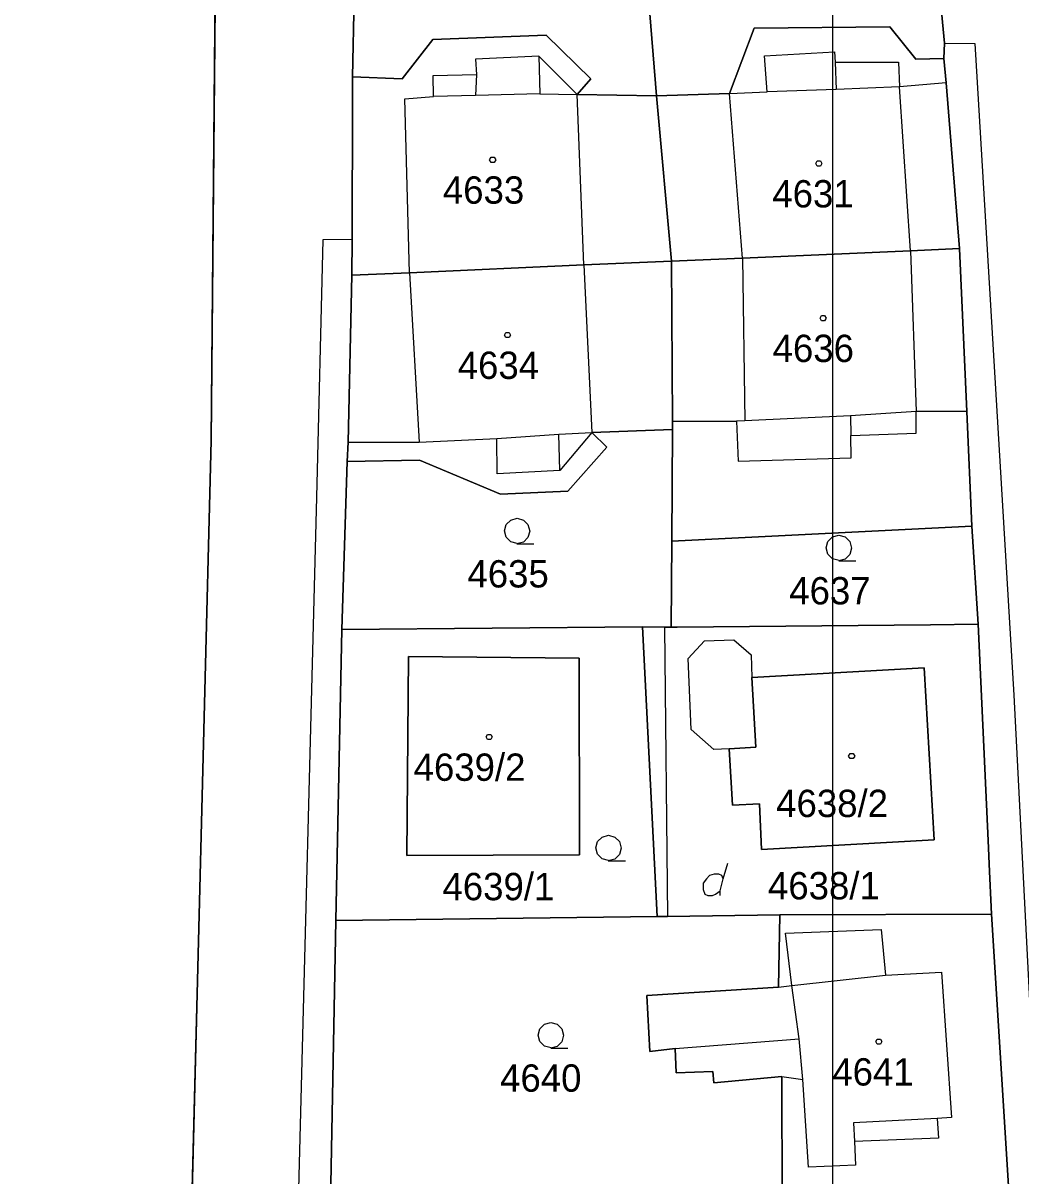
# Model space of a CAD drawing. Extents: x -263587 to -261993, y -1238795 to -1236748.
# Drawn here: x -262742.4 to -262684, y -1237554.8 to -1237487.3 of the extents above; entities that cross this region are included whole.
import ezdxf

# ---------------------------------------------------------------- set-up
doc = ezdxf.new("R2010")
doc.units = 0
for name, color, linetype in [('Vrstva 1', 7, 'Continuous'), ('Vrstva 2', 7, 'Continuous'), ('Vrstva 3', 7, 'Continuous'), ('Vrstva 51', 7, 'Continuous')]:
    doc.layers.add(name, color=color, linetype=linetype)

msp = doc.modelspace()

# ---------------------------------------------------------------- linework, layer by layer
at = {"layer": 'Vrstva 1'}
for p, q in [((-262731.39, -1237511.76), (-262731.08, -1237477.74)), ((-262731.08, -1237477.74), (-262731.39, -1237511.76)), ((-262689.31, -1237479.28), (-262688.48, -1237488.5)), ((-262688.48, -1237488.5), (-262689.31, -1237479.28)), ((-262705.33, -1237491.59), (-262706.28, -1237479.89)), ((-262706.28, -1237479.89), (-262705.33, -1237491.59)), ((-262723.11, -1237490.47), (-262722.91, -1237480.33)), ((-262722.91, -1237480.33), (-262723.11, -1237490.47)), ((-262711.79, -1237488.04), (-262718.41, -1237488.29)), ((-262718.41, -1237488.29), (-262711.79, -1237488.04)), ((-262709.18, -1237490.59), (-262711.79, -1237488.04)), ((-262711.79, -1237488.04), (-262709.18, -1237490.59)), ((-262701.05, -1237491.45), (-262699.62, -1237487.63)), ((-262699.62, -1237487.63), (-262701.05, -1237491.45)), ((-262699.62, -1237487.63), (-262691.67, -1237487.54)), ((-262691.67, -1237487.54), (-262699.62, -1237487.63)), ((-262691.67, -1237487.54), (-262690.15, -1237489.44)), ((-262690.15, -1237489.44), (-262691.67, -1237487.54)), ((-262718.41, -1237488.29), (-262720.21, -1237490.6)), ((-262720.21, -1237490.6), (-262718.41, -1237488.29)), ((-262688.48, -1237488.5), (-262688.52, -1237489.4)), ((-262688.52, -1237489.4), (-262688.48, -1237488.5)), ((-262688.48, -1237488.5), (-262686.71, -1237488.52)), ((-262686.71, -1237488.52), (-262684.42, -1237526.68)), ((-262712.22, -1237489.27), (-262715.92, -1237489.44)), ((-262715.92, -1237489.44), (-262715.86, -1237490.34)), ((-262709.98, -1237491.5), (-262712.22, -1237489.27)), ((-262712.22, -1237489.27), (-262712.16, -1237491.46)), ((-262699.01, -1237489.25), (-262694.91, -1237489.01)), ((-262698.86, -1237491.36), (-262699.01, -1237489.25)), ((-262694.91, -1237489.01), (-262694.88, -1237489.62)), ((-262690.15, -1237489.44), (-262688.52, -1237489.4)), ((-262688.52, -1237489.4), (-262690.15, -1237489.44)), ((-262688.52, -1237489.4), (-262688.38, -1237490.82)), ((-262688.38, -1237490.82), (-262688.52, -1237489.4)), ((-262694.88, -1237489.62), (-262694.81, -1237491.21)), ((-262694.88, -1237489.62), (-262691.17, -1237489.62)), ((-262691.17, -1237489.62), (-262691.12, -1237491.05)), ((-262720.21, -1237490.6), (-262723.11, -1237490.47)), ((-262723.11, -1237490.47), (-262720.21, -1237490.6)), ((-262723.11, -1237491.85), (-262723.11, -1237490.47)), ((-262723.11, -1237490.47), (-262723.11, -1237491.85)), ((-262718.39, -1237490.4), (-262715.86, -1237490.34)), ((-262718.37, -1237491.62), (-262718.39, -1237490.4)), ((-262715.86, -1237490.34), (-262715.92, -1237491.56)), ((-262709.98, -1237491.5), (-262709.18, -1237490.59)), ((-262709.18, -1237490.59), (-262709.98, -1237491.5)), ((-262688.38, -1237490.82), (-262691.12, -1237491.05)), ((-262688.38, -1237490.82), (-262687.6, -1237500.52)), ((-262687.6, -1237500.52), (-262688.38, -1237490.82)), ((-262712.16, -1237491.46), (-262715.92, -1237491.56)), ((-262712.16, -1237491.46), (-262709.98, -1237491.5)), ((-262705.33, -1237491.59), (-262709.98, -1237491.5)), ((-262709.98, -1237491.5), (-262705.33, -1237491.59)), ((-262709.59, -1237501.48), (-262709.98, -1237491.5)), ((-262705.33, -1237491.59), (-262701.05, -1237491.45)), ((-262701.05, -1237491.45), (-262705.33, -1237491.59)), ((-262701.05, -1237491.45), (-262698.86, -1237491.36)), ((-262700.29, -1237501.09), (-262701.05, -1237491.45)), ((-262694.81, -1237491.21), (-262698.86, -1237491.36)), ((-262691.12, -1237491.05), (-262694.81, -1237491.21)), ((-262690.47, -1237500.66), (-262691.12, -1237491.05)), ((-262723.14, -1237499.99), (-262723.11, -1237491.85)), ((-262723.11, -1237491.85), (-262723.14, -1237499.99)), ((-262720.06, -1237491.76), (-262718.37, -1237491.62)), ((-262719.79, -1237501.94), (-262720.06, -1237491.76)), ((-262715.92, -1237491.56), (-262718.37, -1237491.62)), ((-262704.45, -1237501.26), (-262705.33, -1237491.59)), ((-262705.33, -1237491.59), (-262704.45, -1237501.26)), ((-262724.85, -1237500.02), (-262725.22, -1237515.08)), ((-262723.14, -1237499.99), (-262724.85, -1237500.02)), ((-262723.15, -1237502.09), (-262723.14, -1237499.99)), ((-262723.14, -1237499.99), (-262723.15, -1237502.09)), ((-262690.47, -1237500.66), (-262700.29, -1237501.09)), ((-262700.29, -1237501.09), (-262690.47, -1237500.66)), ((-262687.6, -1237500.52), (-262690.47, -1237500.66)), ((-262690.47, -1237500.66), (-262687.6, -1237500.52)), ((-262690.47, -1237500.66), (-262690.13, -1237510.06)), ((-262687.6, -1237500.52), (-262687.17, -1237510.07)), ((-262687.17, -1237510.07), (-262687.6, -1237500.52)), ((-262719.79, -1237501.94), (-262709.59, -1237501.48)), ((-262709.59, -1237501.48), (-262719.79, -1237501.94)), ((-262709.59, -1237501.48), (-262704.45, -1237501.26)), ((-262704.45, -1237501.26), (-262709.59, -1237501.48)), ((-262709.59, -1237501.48), (-262709.12, -1237511.29)), ((-262700.29, -1237501.09), (-262704.45, -1237501.26)), ((-262704.45, -1237501.26), (-262700.29, -1237501.09)), ((-262704.39, -1237510.63), (-262704.45, -1237501.26)), ((-262704.45, -1237501.26), (-262704.39, -1237510.63)), ((-262700.29, -1237501.09), (-262700.17, -1237510.62)), ((-262723.37, -1237511.87), (-262723.15, -1237502.09)), ((-262723.15, -1237502.09), (-262723.37, -1237511.87)), ((-262723.15, -1237502.09), (-262719.79, -1237501.94)), ((-262719.79, -1237501.94), (-262723.15, -1237502.09)), ((-262719.79, -1237501.94), (-262719.21, -1237511.86)), ((-262693.97, -1237510.33), (-262700.17, -1237510.62)), ((-262690.13, -1237510.06), (-262693.97, -1237510.33)), ((-262693.97, -1237510.33), (-262693.96, -1237511.48)), ((-262687.17, -1237510.07), (-262690.13, -1237510.06)), ((-262690.13, -1237511.34), (-262690.13, -1237510.06)), ((-262687.17, -1237510.07), (-262686.87, -1237516.78)), ((-262686.87, -1237516.78), (-262687.17, -1237510.07)), ((-262704.4, -1237511.12), (-262704.39, -1237510.63)), ((-262704.39, -1237510.63), (-262704.4, -1237511.12)), ((-262704.39, -1237510.63), (-262700.64, -1237510.64)), ((-262700.17, -1237510.62), (-262700.64, -1237510.64)), ((-262700.64, -1237510.64), (-262700.55, -1237512.98)), ((-262732.21, -1237544.17), (-262731.39, -1237511.76)), ((-262731.39, -1237511.76), (-262732.21, -1237544.17)), ((-262719.21, -1237511.86), (-262714.68, -1237511.65)), ((-262714.68, -1237511.65), (-262711.05, -1237511.4)), ((-262714.66, -1237513.72), (-262714.68, -1237511.65)), ((-262711.05, -1237511.4), (-262709.12, -1237511.29)), ((-262710.98, -1237513.53), (-262711.05, -1237511.4)), ((-262709.12, -1237511.29), (-262710.98, -1237513.53)), ((-262704.4, -1237511.12), (-262709.12, -1237511.29)), ((-262709.12, -1237511.29), (-262704.4, -1237511.12)), ((-262709.12, -1237511.29), (-262708.24, -1237512.15)), ((-262708.24, -1237512.15), (-262709.12, -1237511.29)), ((-262704.43, -1237517.66), (-262704.4, -1237511.12)), ((-262704.4, -1237511.12), (-262704.43, -1237517.66)), ((-262693.96, -1237511.48), (-262690.13, -1237511.34)), ((-262693.94, -1237512.77), (-262693.96, -1237511.48)), ((-262723.43, -1237512.99), (-262723.37, -1237511.87)), ((-262723.37, -1237511.87), (-262723.43, -1237512.99)), ((-262723.37, -1237511.87), (-262719.21, -1237511.86)), ((-262708.24, -1237512.15), (-262710.52, -1237514.74)), ((-262710.52, -1237514.74), (-262708.24, -1237512.15)), ((-262723.74, -1237522.83), (-262723.43, -1237512.99)), ((-262723.43, -1237512.99), (-262723.74, -1237522.83)), ((-262719.19, -1237512.91), (-262723.43, -1237512.99)), ((-262723.43, -1237512.99), (-262719.19, -1237512.91)), ((-262714.45, -1237514.91), (-262719.19, -1237512.91)), ((-262719.19, -1237512.91), (-262714.45, -1237514.91)), ((-262700.55, -1237512.98), (-262693.94, -1237512.77)), ((-262710.98, -1237513.53), (-262714.66, -1237513.72)), ((-262725.22, -1237515.08), (-262726.58, -1237567.18)), ((-262710.52, -1237514.74), (-262714.45, -1237514.91)), ((-262714.45, -1237514.91), (-262710.52, -1237514.74)), ((-262686.87, -1237516.78), (-262704.43, -1237517.66)), ((-262704.43, -1237517.66), (-262686.87, -1237516.78)), ((-262686.87, -1237516.78), (-262686.51, -1237522.52)), ((-262686.51, -1237522.52), (-262686.87, -1237516.78)), ((-262704.47, -1237522.69), (-262704.43, -1237517.66)), ((-262704.43, -1237517.66), (-262704.47, -1237522.69)), ((-262689.29, -1237522.55), (-262704.12, -1237522.69)), ((-262704.12, -1237522.69), (-262689.29, -1237522.55)), ((-262686.51, -1237522.52), (-262689.29, -1237522.55)), ((-262689.29, -1237522.55), (-262686.51, -1237522.52)), ((-262685.9, -1237535.61), (-262686.51, -1237522.52)), ((-262686.51, -1237522.52), (-262685.9, -1237535.61)), ((-262724.09, -1237539.86), (-262723.74, -1237522.83)), ((-262723.74, -1237522.83), (-262724.09, -1237539.86)), ((-262706.14, -1237522.67), (-262723.74, -1237522.83)), ((-262723.74, -1237522.83), (-262706.14, -1237522.67)), ((-262704.86, -1237522.69), (-262706.14, -1237522.67)), ((-262706.14, -1237522.67), (-262705.3, -1237539.64)), ((-262705.3, -1237539.64), (-262706.14, -1237522.67)), ((-262706.14, -1237522.67), (-262704.86, -1237522.69)), ((-262704.47, -1237522.69), (-262704.86, -1237522.69)), ((-262704.86, -1237522.69), (-262704.47, -1237522.69)), ((-262704.86, -1237522.69), (-262704.68, -1237539.63)), ((-262704.12, -1237522.69), (-262704.47, -1237522.69)), ((-262704.47, -1237522.69), (-262704.12, -1237522.69)), ((-262703.48, -1237524.53), (-262702.52, -1237523.5)), ((-262702.52, -1237523.5), (-262700.8, -1237523.43)), ((-262700.8, -1237523.43), (-262699.8, -1237524.32)), ((-262719.85, -1237524.42), (-262719.94, -1237536.07)), ((-262719.94, -1237536.07), (-262719.85, -1237524.42)), ((-262709.86, -1237524.51), (-262719.85, -1237524.42)), ((-262719.85, -1237524.42), (-262709.86, -1237524.51)), ((-262709.83, -1237536.02), (-262709.86, -1237524.51)), ((-262709.86, -1237524.51), (-262709.83, -1237536.02)), ((-262703.31, -1237528.68), (-262703.48, -1237524.53)), ((-262699.8, -1237524.32), (-262699.75, -1237525.64)), ((-262699.75, -1237525.64), (-262689.66, -1237525.07)), ((-262689.66, -1237525.07), (-262699.75, -1237525.64)), ((-262689.66, -1237525.07), (-262689.09, -1237535.15)), ((-262689.09, -1237535.15), (-262689.66, -1237525.07)), ((-262699.52, -1237529.72), (-262699.75, -1237525.64)), ((-262699.75, -1237525.64), (-262699.52, -1237529.72)), ((-262684.42, -1237526.68), (-262682.75, -1237559.3)), ((-262701.98, -1237529.85), (-262703.31, -1237528.68)), ((-262701.08, -1237529.81), (-262701.98, -1237529.85)), ((-262701.08, -1237529.81), (-262699.52, -1237529.72)), ((-262699.52, -1237529.72), (-262701.08, -1237529.81)), ((-262700.89, -1237533.11), (-262701.08, -1237529.81)), ((-262701.08, -1237529.81), (-262700.89, -1237533.11)), ((-262699.31, -1237533.03), (-262700.89, -1237533.11)), ((-262700.89, -1237533.11), (-262699.31, -1237533.03)), ((-262699.18, -1237535.72), (-262699.31, -1237533.03)), ((-262699.31, -1237533.03), (-262699.18, -1237535.72)), ((-262689.09, -1237535.15), (-262699.18, -1237535.72)), ((-262699.18, -1237535.72), (-262689.09, -1237535.15)), ((-262719.94, -1237536.07), (-262709.83, -1237536.02)), ((-262709.83, -1237536.02), (-262719.94, -1237536.07)), ((-262685.86, -1237536.57), (-262685.9, -1237535.61)), ((-262685.9, -1237535.61), (-262685.86, -1237536.57)), ((-262701.42, -1237537.42), (-262701.15, -1237536.52)), ((-262685.72, -1237539.5), (-262685.86, -1237536.57)), ((-262685.86, -1237536.57), (-262685.72, -1237539.5)), ((-262724.42, -1237556.81), (-262724.09, -1237539.86)), ((-262724.09, -1237539.86), (-262724.42, -1237556.81)), ((-262705.3, -1237539.64), (-262724.09, -1237539.86)), ((-262724.09, -1237539.86), (-262705.3, -1237539.64)), ((-262705.3, -1237539.64), (-262704.68, -1237539.63)), ((-262704.68, -1237539.63), (-262705.3, -1237539.64)), ((-262704.68, -1237539.63), (-262698.12, -1237539.54)), ((-262698.12, -1237539.54), (-262704.68, -1237539.63)), ((-262698.2, -1237543.77), (-262698.12, -1237539.54)), ((-262698.12, -1237539.54), (-262698.2, -1237543.77)), ((-262698.12, -1237539.54), (-262685.72, -1237539.5)), ((-262685.72, -1237539.5), (-262698.12, -1237539.54)), ((-262685.72, -1237539.5), (-262684.63, -1237556.95)), ((-262684.63, -1237556.95), (-262685.72, -1237539.5)), ((-262697.78, -1237540.61), (-262692.19, -1237540.39)), ((-262697.41, -1237543.68), (-262697.78, -1237540.61)), ((-262692.19, -1237540.39), (-262691.93, -1237543.07)), ((-262697.41, -1237543.68), (-262691.93, -1237543.07)), ((-262691.93, -1237543.07), (-262688.66, -1237542.9)), ((-262688.66, -1237542.9), (-262688.06, -1237551.41)), ((-262732.74, -1237565.04), (-262732.21, -1237544.17)), ((-262732.21, -1237544.17), (-262732.74, -1237565.04)), ((-262705.9, -1237544.26), (-262698.2, -1237543.77)), ((-262698.2, -1237543.77), (-262705.9, -1237544.26)), ((-262698.2, -1237543.77), (-262697.41, -1237543.68)), ((-262696.99, -1237546.79), (-262697.41, -1237543.68)), ((-262705.72, -1237547.53), (-262705.9, -1237544.26)), ((-262705.9, -1237544.26), (-262705.72, -1237547.53)), ((-262704.23, -1237547.37), (-262696.99, -1237546.79)), ((-262696.77, -1237549.17), (-262696.99, -1237546.79)), ((-262704.23, -1237547.37), (-262705.72, -1237547.53)), ((-262705.72, -1237547.53), (-262704.23, -1237547.37)), ((-262704.18, -1237548.78), (-262704.23, -1237547.37)), ((-262704.23, -1237547.37), (-262704.18, -1237548.78)), ((-262702.03, -1237548.7), (-262704.18, -1237548.78)), ((-262704.18, -1237548.78), (-262702.03, -1237548.7)), ((-262701.97, -1237549.38), (-262702.03, -1237548.7)), ((-262702.03, -1237548.7), (-262701.97, -1237549.38)), ((-262697.99, -1237549), (-262701.97, -1237549.38)), ((-262701.97, -1237549.38), (-262697.99, -1237549)), ((-262697.98, -1237556.86), (-262697.99, -1237549)), ((-262697.99, -1237549), (-262697.98, -1237556.86)), ((-262697.99, -1237549), (-262696.77, -1237549.17)), ((-262696.44, -1237554.3), (-262696.77, -1237549.17)), ((-262688.91, -1237551.46), (-262693.8, -1237551.71)), ((-262688.06, -1237551.41), (-262688.91, -1237551.46)), ((-262688.91, -1237551.46), (-262688.83, -1237552.62)), ((-262693.8, -1237551.71), (-262693.75, -1237552.81)), ((-262688.83, -1237552.62), (-262693.75, -1237552.81)), ((-262693.75, -1237552.81), (-262693.69, -1237554.19)), ((-262693.69, -1237554.19), (-262696.44, -1237554.3))]:
    msp.add_line(p, q, dxfattribs=at)
for points in [[(-262714.83, -1237495.18), (-262714.74, -1237495.33), (-262714.83, -1237495.48), (-262715.01, -1237495.48), (-262715.1, -1237495.33), (-262715.01, -1237495.18)], [(-262695.74, -1237495.4), (-262695.65, -1237495.55), (-262695.74, -1237495.7), (-262695.92, -1237495.7), (-262696.01, -1237495.55), (-262695.92, -1237495.4)], [(-262695.49, -1237504.45), (-262695.4, -1237504.6), (-262695.49, -1237504.75), (-262695.67, -1237504.75), (-262695.76, -1237504.6), (-262695.67, -1237504.45)], [(-262713.96, -1237505.44), (-262713.87, -1237505.59), (-262713.96, -1237505.74), (-262714.14, -1237505.74), (-262714.23, -1237505.59), (-262714.14, -1237505.44)], [(-262715.03, -1237528.97), (-262714.94, -1237529.12), (-262715.03, -1237529.27), (-262715.21, -1237529.27), (-262715.3, -1237529.12), (-262715.21, -1237528.97)], [(-262693.82, -1237530.09), (-262693.73, -1237530.24), (-262693.82, -1237530.39), (-262694, -1237530.39), (-262694.09, -1237530.24), (-262694, -1237530.09)], [(-262692.23, -1237546.81), (-262692.14, -1237546.96), (-262692.23, -1237547.11), (-262692.41, -1237547.11), (-262692.5, -1237546.96), (-262692.41, -1237546.81)]]:
    msp.add_lwpolyline(points, close=True, dxfattribs=at)
for points in [[(-262713.48, -1237517.8), (-262713.86, -1237517.7), (-262714.13, -1237517.43), (-262714.23, -1237517.06), (-262714.13, -1237516.69), (-262713.86, -1237516.42), (-262713.49, -1237516.32), (-262713.12, -1237516.42), (-262712.85, -1237516.69), (-262712.75, -1237517.07), (-262712.85, -1237517.45), (-262713.12, -1237517.72), (-262713.5, -1237517.82), (-262712.5, -1237517.82)], [(-262694.65, -1237518.79), (-262695.03, -1237518.69), (-262695.3, -1237518.42), (-262695.4, -1237518.05), (-262695.3, -1237517.68), (-262695.03, -1237517.41), (-262694.66, -1237517.31), (-262694.29, -1237517.41), (-262694.02, -1237517.68), (-262693.92, -1237518.06), (-262694.02, -1237518.44), (-262694.29, -1237518.71), (-262694.67, -1237518.81), (-262693.67, -1237518.81)], [(-262708.13, -1237536.36), (-262708.51, -1237536.26), (-262708.78, -1237535.99), (-262708.88, -1237535.62), (-262708.78, -1237535.25), (-262708.51, -1237534.98), (-262708.14, -1237534.88), (-262707.77, -1237534.98), (-262707.5, -1237535.25), (-262707.4, -1237535.63), (-262707.5, -1237536.01), (-262707.77, -1237536.28), (-262708.15, -1237536.38), (-262707.15, -1237536.38)], [(-262701.6, -1237538.41), (-262701.6, -1237538.14), (-262701.42, -1237537.42), (-262701.51, -1237537.24), (-262701.69, -1237537.15), (-262701.96, -1237537.15), (-262702.23, -1237537.24), (-262702.41, -1237537.42), (-262702.59, -1237537.69), (-262702.59, -1237538.05), (-262702.5, -1237538.32), (-262702.32, -1237538.41), (-262702.05, -1237538.41), (-262701.87, -1237538.32), (-262701.6, -1237538.14)], [(-262711.5, -1237547.32), (-262711.88, -1237547.22), (-262712.15, -1237546.95), (-262712.25, -1237546.58), (-262712.15, -1237546.21), (-262711.88, -1237545.94), (-262711.51, -1237545.84), (-262711.14, -1237545.94), (-262710.87, -1237546.21), (-262710.77, -1237546.59), (-262710.87, -1237546.97), (-262711.14, -1237547.24), (-262711.52, -1237547.34), (-262710.52, -1237547.34)]]:
    msp.add_lwpolyline(points, dxfattribs=at)
at = {"layer": 'Vrstva 2'}
msp.add_lwpolyline([(-262753.33, -1237625.635), (-262745.26, -1237606.9), (-262735.28, -1237583.83), (-262733.58, -1237576.98), (-262732.74, -1237565.04), (-262732.21, -1237544.17), (-262731.39, -1237511.76), (-262730.95, -1237461.27), (-262730.63, -1237425.62), (-262730.13, -1237378.82), (-262729.58, -1237341.73), (-262728.955, -1237306.535), (-262728.75, -1237298.15)], dxfattribs=at)
at = {"layer": 'Vrstva 3'}
msp.add_lwpolyline([(-262744.25, -1237230.5), (-262727.51, -1237252.7), (-262720.535, -1237260.115), (-262719.819, -1237263.32), (-262725.18, -1237264.54), (-262731.17, -1237266.01), (-262730.23, -1237271.65), (-262726.66, -1237279.47), (-262728.52, -1237280.61), (-262728.56, -1237282.52), (-262728.73, -1237295.74), (-262728.75, -1237298.15), (-262729.16, -1237314.92), (-262729.45, -1237331.3), (-262729.71, -1237352.16), (-262730.55, -1237405.48), (-262730.82, -1237444.8), (-262731.08, -1237477.74), (-262731.39, -1237511.76), (-262732.21, -1237544.17), (-262732.74, -1237565.04), (-262733.58, -1237576.98), (-262735.28, -1237583.83), (-262745.26, -1237606.9)], dxfattribs=at)
at = {"layer": 'Vrstva 51'}
msp.add_lwpolyline([(-262992.03, -1237088.09), (-262695.03, -1237088.09), (-262695.03, -1238768.09), (-262992.03, -1238768.09)], close=True, dxfattribs=at)

# ---------------------------------------------------------------- texts
at = {"layer": 'Vrstva 1'}
for s, p in [('4633', (-262717.832, -1237497.9)), ('4631', (-262698.553, -1237498.12)), ('4636', (-262698.536, -1237507.17)), ('4634', (-262716.962, -1237508.16)), ('4635', (-262716.392, -1237520.37)), ('4637', (-262697.562, -1237521.36)), ('4639/2', (-262719.543, -1237531.69)), ('4638/2', (-262698.327, -1237533.81)), ('4639/1', (-262717.854, -1237538.68)), ('4638/1', (-262698.808, -1237538.63)), ('4641', (-262695.043, -1237549.53)), ('4640', (-262714.481, -1237549.89))]:
    msp.add_text(s, height=1.6, dxfattribs=at).set_placement(p)

doc.saveas('drawing.dxf')
